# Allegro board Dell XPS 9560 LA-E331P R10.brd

Outline 352.7 x 122.8 mm; copper layers: TOP, GND1, IN1, IN2, GND2, IN3, IN4, VCC, IN5, IN6, GND3, BOTTOM. Coordinates in mm from the lower left corner of the outline.

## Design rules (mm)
net group CLK_PCIE_CR: nets CLK_PCIE_CR CLK_PCIE_CR#
net group CLK_PCIE_SSD: nets CLK_PCIE_SSD CLK_PCIE_SSD#
net group CLK_PCIE_WLAN: nets CLK_PCIE_WLAN CLK_PCIE_WLAN#
net group CRITICAL: nets CLINK_CLK SUSCLK
net group CSS_1: nets CSSN_1 CSSP_1
net group DDI1_CPU_AUX: nets DDI1_CPU_AUXN DDI1_CPU_AUXP
net group DDI1DDI1_CPU_AUX_C: nets DDI1_CPU_AUXN_C DDI1_CPU_AUXP_C
net group DDI1DDI1_HTX_TBRX_0: nets DDI1_HTX_TBRX_N0 DDI1_HTX_TBRX_P0
net group DDI1DDI1_HTX_TBRX_0_C: nets DDI1_HTX_TBRX_N0_C DDI1_HTX_TBRX_P0_C
net group DDI1DDI1_HTX_TBRX_1: nets DDI1_HTX_TBRX_N1 DDI1_HTX_TBRX_P1
net group DDI1DDI1_HTX_TBRX_1_C: nets DDI1_HTX_TBRX_N1_C DDI1_HTX_TBRX_P1_C
net group DDI1DDI1_HTX_TBRX_2: nets DDI1_HTX_TBRX_N2 DDI1_HTX_TBRX_P2
net group DDI1DDI1_HTX_TBRX_2_C: nets DDI1_HTX_TBRX_N2_C DDI1_HTX_TBRX_P2_C
net group DDI1DDI1_HTX_TBRX_3: nets DDI1_HTX_TBRX_N3 DDI1_HTX_TBRX_P3
net group DDI1DDI1_HTX_TBRX_3_C: nets DDI1_HTX_TBRX_N3_C DDI1_HTX_TBRX_P3_C
net group DDI1DDI2_CPU_AUX: nets DDI2_CPU_AUXN DDI2_CPU_AUXP
net group DDI1DDI2_CPU_AUX_C: nets DDI2_CPU_AUXN_C DDI2_CPU_AUXP_C
net group DDI1DDI2_HTX_TBRX_0: nets DDI2_HTX_TBRX_N0 DDI2_HTX_TBRX_P0
net group DDI1DDI2_HTX_TBRX_0_C: nets DDI2_HTX_TBRX_N0_C DDI2_HTX_TBRX_P0_C
net group DDI1DDI2_HTX_TBRX_1: nets DDI2_HTX_TBRX_N1 DDI2_HTX_TBRX_P1
net group DDI1DDI2_HTX_TBRX_1_C: nets DDI2_HTX_TBRX_N1_C DDI2_HTX_TBRX_P1_C
net group DDI1DDI2_HTX_TBRX_2: nets DDI2_HTX_TBRX_N2 DDI2_HTX_TBRX_P2
net group DDI1DDI2_HTX_TBRX_2_C: nets DDI2_HTX_TBRX_N2_C DDI2_HTX_TBRX_P2_C
net group DDI1DDI2_HTX_TBRX_3: nets DDI2_HTX_TBRX_N3 DDI2_HTX_TBRX_P3
net group DDI1DDI2_HTX_TBRX_3_C: nets DDI2_HTX_TBRX_N3_C DDI2_HTX_TBRX_P3_C
net group DIFFPAIR0: nets DDC_CLK_HDMI DDC_DAT_HDMI
net group DIFFPAIR35: nets USB3TN1_D- USB3TP1_D+
net group DIFFPAIR36: nets USB3RN1_D- USB3RP1_D+
net group DIFFPAIR47: nets SD_LN1_M SD_LN1_P
net group DIFFPAIR48: nets SD_LN0_M SD_LN0_P
net group DIFFPAIR49: nets SD_RCLK_M SD_RCLK_P
net group DIFFPAIR51: nets USB3RN1_RE USB3RP1_RE
net group DIFFPAIR57: nets DOCK_TNY_SMB_CLK DOCK_TNY_SMB_DAT
net group DIFFPAIR59: nets TBTA_I2C_C_N TBTA_I2C_C_P
net group DIFFPAIR60: nets TBTA_USB2_D_N_C TBTA_USB2_D_P_C
net group DIFFPAIR61: nets TBT_USB3_TX0_N TBT_USB3_TX0_P
net group DIFFPAIR62: nets TBT_USB3_TX1_N TBT_USB3_TX1_P
net group DIFFPAIR63: nets TBT_DDC_CLK TBT_DDC_DATA
net group DIFFPAIR64: nets XTAL_OUT XTALIN
net group EDP_AUXP_C: nets EDP_AUXN_C EDP_AUXP_C
net group EDP_TX2_R: nets EDP_TXN2_R EDP_TXP2_R
net group EDP_TX3_R: nets EDP_TXN3_R EDP_TXP3_R
net group FBA_CLK0: nets FBA_CLK0 FBA_CLK0#
net group FBA_CLK1: nets FBA_CLK1 FBA_CLK1#
net group FBA_WCK0: nets FBA_WCK0 FBA_WCK0_N
net group FBA_WCK1: nets FBA_WCK1 FBA_WCK1_N
net group FBA_WCK2: nets FBA_WCK2 FBA_WCK2_N
net group FBA_WCK3: nets FBA_WCK3 FBA_WCK3_N
net group FBC_CLK0: nets FBC_CLK0 FBC_CLK0#
net group FBC_CLK1: nets FBC_CLK1 FBC_CLK1#
net group FBC_WCK0: nets FBC_WCK0 FBC_WCK0_N
net group FBC_WCK1: nets FBC_WCK1 FBC_WCK1_N
net group FBC_WCK2: nets FBC_WCK2 FBC_WCK2_N
net group FBC_WCK3: nets FBC_WCK3 FBC_WCK3_N
net group PCIE_PRX_CARDTX_2: nets PCIE_PRX_CARDTX_N2 PCIE_PRX_CARDTX_P2
net group PCIE_PRX_CARDTX_2_C: nets PCIE_PRX_CARDTX_N2_C PCIE_PRX_CARDTX_P2_C
net group PCIE_PRX_SSDTX_10: nets PCIE_PRX_SSDTX_N10 PCIE_PRX_SSDTX_P10
net group PCIE_PRX_SSDTX_11: nets PCIE_PRX_SSDTX_N11 PCIE_PRX_SSDTX_P11
net group PCIE_PRX_SSDTX_12: nets PCIE_PRX_SSDTX_N12 PCIE_PRX_SSDTX_P12
net group PCIE_PRX_TBTX_15: nets PCIE_PRX_TBTX_N15 PCIE_PRX_TBTX_P15
net group PCIE_PRX_TBTX_16: nets PCIE_PRX_TBTX_N16 PCIE_PRX_TBTX_P16
net group PCIE_PRX_WLANTX_1: nets PCIE_PRX_WLANTX_N1 PCIE_PRX_WLANTX_P1
net group PCIE_PTX_CARDRX_2: nets PCIE_PTX_CARDRX_N2 PCIE_PTX_CARDRX_P2
net group PCIE_PTX_CARDRX_2_C: nets PCIE_PTX_CARDRX_N2_C PCIE_PTX_CARDRX_P2_C
net group PCIE_PTX_SSDRX_10: nets PCIE_PTX_SSDRX_N10 PCIE_PTX_SSDRX_P10
net group PCIE_PTX_SSDRX_10_C: nets PCIE_PTX_SSDRX_N10_C PCIE_PTX_SSDRX_P10_C
net group PCIE_PTX_SSDRX_11: nets PCIE_PTX_SSDRX_N11 PCIE_PTX_SSDRX_P11
net group PCIE_PTX_SSDRX_11_C: nets PCIE_PTX_SSDRX_N11_C PCIE_PTX_SSDRX_P11_C
net group PCIE_PTX_SSDRX_12: nets PCIE_PTX_SSDRX_N12 PCIE_PTX_SSDRX_P12
net group PCIE_PTX_SSDRX_12_C: nets PCIE_PTX_SSDRX_N12_C PCIE_PTX_SSDRX_P12_C
net group PCIE_PTX_TBRX_15: nets PCIE_PTX_TBRX_N15 PCIE_PTX_TBRX_P15
net group PCIE_PTX_TBRX_16: nets PCIE_PTX_TBRX_N16 PCIE_PTX_TBRX_P16
net group PCIE_PTX_WLANRX_1: nets PCIE_PTX_WLANRX_N1 PCIE_PTX_WLANRX_P1
net group PCIE_PTX_WLANRX_RE_1: nets PCIE_PTX_WLANRX_RE_N1 PCIE_PTX_WLANRX_RE_P1
net group REF-AGND: nets TBTA_CC1 TBTA_CC2
net group SATA_PRX_DTX_1B: nets SATA_PRX_DTX_N1B SATA_PRX_DTX_P1B
net group SATA_PRX_DTX_1B_RC: nets SATA_PRX_DTX_N1B_RC SATA_PRX_DTX_P1B_RC
net group SATA_PRX_SSDTX_0A: nets SATA_PRX_SSDTX_N0A SATA_PRX_SSDTX_P0A
net group SATA_PTX_DRX_1B: nets SATA_PTX_DRX_N1B SATA_PTX_DRX_P1B
net group SATA_PTX_DRX_1B_RC: nets SATA_PTX_DRX_N1B_RC SATA_PTX_DRX_P1B_RC
net group SATA_PTX_SSDRX_0A: nets SATA_PTX_SSDRX_N0A SATA_PTX_SSDRX_P0A
net group SATA_PTX_SSDRX_0A_C: nets SATA_PTX_SSDRX_N0A_C SATA_PTX_SSDRX_P0A_C
net group SD_RCLK_R: nets SD_RCLK_M_R SD_RCLK_P_R
net group SENSE: nets VCC_SENSE VSS_SENSE
net group SIN_CLK: nets AUD_AZA_CPU_SCLK VGA_CLK_REQ#
net group SMBUS: nets I2CB_SCL I2CB_SDA
net group SPI-CLK: nets PCH_SPI_CLK PCH_SPI_CLK_R
net group THERMTRIP: nets H_THERMTRIP# H_THERMTRIP#_R
net group USBP2_D: nets USBP2_D+ USBP2_D-
net group USBP2_R_D: nets USBP2_R_D+ USBP2_R_D-
net group 12: nets H_PECI UART2_RXD UART2_TXD
net group 15: nets HDA_BITCLK N121029055 N121029061
net group ASY: nets H_CPUPWRGD H_PROCHOT# H_PROCHOT#_R PCH_RSMRST#
net group ASYNCHRONOUS: nets DGPU_HOLD_RST#
net group AUDIO: nets HPOUT_D_L_C HPOUT_D_R_C HPOUT_L HPOUT_L_R1 HPOUT_R HPOUT_R_R2 LINE1-VREFO LINE1_L LINE1_L_C LINE1_R LINE1_R_C MIC1-VREFO_L MIC1-VREFO_R RING2 RING2_L SLEEVE SLEEVE_L
net group CLK_15_20: nets PCI_CLK_LPC1
net group DDI1: nets DDI1_DDPB_CTRLCLK DDI1_DDPB_CTRLDAT DDI1_PCH_HPD
net group DDI2: nets DDI2_DDPC_CTRLCLK DDI2_DDPC_CTRLDAT DDI2_PCH_HPD
net group DDR_CLK: nets M_CLK_DDR0 M_CLK_DDR1 M_CLK_DDR2 M_CLK_DDR3 M_CLK_DDR#0 M_CLK_DDR#1 M_CLK_DDR#2 M_CLK_DDR#3
net group DDR_DQS: nets DDR_A_DQS0 DDR_A_DQS1 DDR_A_DQS2 DDR_A_DQS3 DDR_A_DQS4 DDR_A_DQS5 DDR_A_DQS6 DDR_A_DQS7 DDR_A_DQS#0 DDR_A_DQS#1 DDR_A_DQS#2 DDR_A_DQS#3 DDR_A_DQS#4 DDR_A_DQS#5 DDR_A_DQS#6 DDR_A_DQS#7 DDR_B_DQS0 DDR_B_DQS1 DDR_B_DQS2 DDR_B_DQS3 DDR_B_DQS4 DDR_B_DQS5 DDR_B_DQS6 DDR_B_DQS7 DDR_B_DQS#0 DDR_B_DQS#1 DDR_B_DQS#2 DDR_B_DQS#3 DDR_B_DQS#4 DDR_B_DQS#5 DDR_B_DQS#6 DDR_B_DQS#7
net group DDRA_ADD: nets DDR_A_ACT# DDR_A_ALERT# DDR_A_BG0 DDR_A_BG1 DDR_A_BS0 DDR_A_BS1 DDR_A_CAS# DDR_A_MA0 DDR_A_MA1 DDR_A_MA2 DDR_A_MA3 DDR_A_MA4 DDR_A_MA5 DDR_A_MA6 DDR_A_MA7 DDR_A_MA8 DDR_A_MA9 DDR_A_MA10 DDR_A_MA11 DDR_A_MA12 DDR_A_MA13 DDR_A_PAR DDR_A_RAS# DDR_A_WE#
net group DDRA_CTRL: nets DDR_CKE0_DIMMA DDR_CKE1_DIMMA DDR_CS0_DIMMA# DDR_CS1_DIMMA# M_ODT0 M_ODT1
net group DDRA_D0: nets DDR_A_D0 DDR_A_D1 DDR_A_D2 DDR_A_D3 DDR_A_D4 DDR_A_D5 DDR_A_D6 DDR_A_D7
net group DDRA_D1: nets DDR_A_D8 DDR_A_D9 DDR_A_D10 DDR_A_D11 DDR_A_D12 DDR_A_D13 DDR_A_D14 DDR_A_D15
net group DDRA_D2: nets DDR_A_D16 DDR_A_D17 DDR_A_D18 DDR_A_D19 DDR_A_D20 DDR_A_D21 DDR_A_D22 DDR_A_D23
net group DDRA_D3: nets DDR_A_D24 DDR_A_D25 DDR_A_D26 DDR_A_D27 DDR_A_D28 DDR_A_D29 DDR_A_D30 DDR_A_D31
net group DDRA_D4: nets DDR_A_D32 DDR_A_D33 DDR_A_D34 DDR_A_D35 DDR_A_D36 DDR_A_D37 DDR_A_D38 DDR_A_D39
net group DDRA_D5: nets DDR_A_D40 DDR_A_D41 DDR_A_D42 DDR_A_D43 DDR_A_D44 DDR_A_D45 DDR_A_D46 DDR_A_D47
net group DDRA_D6: nets DDR_A_D48 DDR_A_D49 DDR_A_D50 DDR_A_D51 DDR_A_D52 DDR_A_D53 DDR_A_D54 DDR_A_D55
net group DDRA_D7: nets DDR_A_D56 DDR_A_D57 DDR_A_D58 DDR_A_D59 DDR_A_D60 DDR_A_D61 DDR_A_D62 DDR_A_D63
net group DDRB_ADD: nets DDR_B_ACT# DDR_B_ALERT# DDR_B_BG0 DDR_B_BG1 DDR_B_BS0 DDR_B_BS1 DDR_B_CAS# DDR_B_MA0 DDR_B_MA1 DDR_B_MA2 DDR_B_MA3 DDR_B_MA4 DDR_B_MA5 DDR_B_MA6 DDR_B_MA7 DDR_B_MA8 DDR_B_MA9 DDR_B_MA10 DDR_B_MA11 DDR_B_MA12 DDR_B_MA13 DDR_B_PAR DDR_B_RAS# DDR_B_WE#
net group DDRB_CTRL: nets DDR_CKE2_DIMMB DDR_CKE3_DIMMB DDR_CS2_DIMMB# DDR_CS3_DIMMB# M_ODT2 M_ODT3
net group DDRB_D0: nets DDR_B_D0 DDR_B_D1 DDR_B_D2 DDR_B_D3 DDR_B_D4 DDR_B_D5 DDR_B_D6 DDR_B_D7
net group DDRB_D1: nets DDR_B_D8 DDR_B_D9 DDR_B_D10 DDR_B_D11 DDR_B_D12 DDR_B_D13 DDR_B_D14 DDR_B_D15
net group DDRB_D2: nets DDR_B_D16 DDR_B_D17 DDR_B_D18 DDR_B_D19 DDR_B_D20 DDR_B_D21 DDR_B_D22 DDR_B_D23
net group DDRB_D3: nets DDR_B_D24 DDR_B_D25 DDR_B_D26 DDR_B_D27 DDR_B_D28 DDR_B_D29 DDR_B_D30 DDR_B_D31
net group DDRB_D4: nets DDR_B_D32 DDR_B_D33 DDR_B_D34 DDR_B_D35 DDR_B_D36 DDR_B_D37 DDR_B_D38 DDR_B_D39
net group DDRB_D5: nets DDR_B_D40 DDR_B_D41 DDR_B_D42 DDR_B_D43 DDR_B_D44 DDR_B_D45 DDR_B_D46 DDR_B_D47
net group DDRB_D6: nets DDR_B_D48 DDR_B_D49 DDR_B_D50 DDR_B_D51 DDR_B_D52 DDR_B_D53 DDR_B_D54 DDR_B_D55
net group DDRB_D7: nets DDR_B_D56 DDR_B_D57 DDR_B_D58 DDR_B_D59 DDR_B_D60 DDR_B_D61 DDR_B_D62 DDR_B_D63
net group DIFFPAIR38: nets USB3RP1
net group DMI: nets DMI_CRX_PTX_N0 DMI_CRX_PTX_N1 DMI_CRX_PTX_N2 DMI_CRX_PTX_N3 DMI_CRX_PTX_P0 DMI_CRX_PTX_P1 DMI_CRX_PTX_P2 DMI_CRX_PTX_P3 DMI_CTX_PRX_N0 DMI_CTX_PRX_N1 DMI_CTX_PRX_N2 DMI_CTX_PRX_N3 DMI_CTX_PRX_P0 DMI_CTX_PRX_P1 DMI_CTX_PRX_P2 DMI_CTX_PRX_P3
net group EDP: nets EDP_AUXN EDP_AUXN_R EDP_AUXP EDP_AUXP_R EDP_COMP EDP_HPD_S EDP_TXN0 EDP_TXN0_C EDP_TXN0_R EDP_TXN1 EDP_TXN1_C EDP_TXN1_R EDP_TXN2 EDP_TXN2_C EDP_TXN3 EDP_TXN3_C EDP_TXP0 EDP_TXP0_C EDP_TXP0_R EDP_TXP1 EDP_TXP1_C EDP_TXP1_R EDP_TXP2 EDP_TXP2_C EDP_TXP3 EDP_TXP3_C
net group FBA_CMD: nets FBA_ABI#_H FBA_ABI#_L FBA_CAS#_H FBA_CAS#_L FBA_CKE_H FBA_CKE_L FBA_CS#_H FBA_CS#_L FBA_MA0_MA10_H FBA_MA0_MA10_L FBA_MA1_MA9_H FBA_MA1_MA9_L FBA_MA2_BA0_H FBA_MA2_BA0_L FBA_MA3_BA3_H FBA_MA3_BA3_L FBA_MA4_BA2_H FBA_MA4_BA2_L FBA_MA5_BA1_H FBA_MA5_BA1_L FBA_MA6_MA11_H FBA_MA6_MA11_L FBA_MA7_MA8_H FBA_MA7_MA8_L FBA_MA12_RFU_H FBA_MA12_RFU_L FBA_RAS#_H FBA_RAS#_L FBA_RST#_H FBA_RST#_L FBA_WE#_H FBA_WE#_L
net group FBA_D0: nets FBA_D0 FBA_D1 FBA_D2 FBA_D3 FBA_D4 FBA_D5 FBA_D6 FBA_D7
net group FBA_D1: nets FBA_D8 FBA_D9 FBA_D10 FBA_D11 FBA_D12 FBA_D13 FBA_D14 FBA_D15
net group FBA_D2: nets FBA_D16 FBA_D17 FBA_D18 FBA_D19 FBA_D20 FBA_D21 FBA_D22 FBA_D23
net group FBA_D3: nets FBA_D24 FBA_D25 FBA_D26 FBA_D27 FBA_D28 FBA_D29 FBA_D30 FBA_D31
net group FBA_D4: nets FBA_D32 FBA_D33 FBA_D34 FBA_D35 FBA_D36 FBA_D37 FBA_D38 FBA_D39
net group FBA_D5: nets FBA_D40 FBA_D41 FBA_D42 FBA_D43 FBA_D44 FBA_D45 FBA_D46 FBA_D47
net group FBA_D6: nets FBA_D48 FBA_D49 FBA_D50 FBA_D51 FBA_D52 FBA_D53 FBA_D54 FBA_D55
net group FBA_D7: nets FBA_D56 FBA_D57 FBA_D58 FBA_D59 FBA_D60 FBA_D61 FBA_D62 FBA_D63
net group FBA_DBI: nets FBA_DBI0# FBA_DBI1# FBA_DBI2# FBA_DBI3# FBA_DBI4# FBA_DBI5# FBA_DBI6# FBA_DBI7#
net group FBA_EDC: nets FBA_EDC0 FBA_EDC1 FBA_EDC2 FBA_EDC3 FBA_EDC4 FBA_EDC5 FBA_EDC6 FBA_EDC7
net group FBC_CMD: nets FBC_ABI#_H FBC_ABI#_L FBC_CAS#_H FBC_CAS#_L FBC_CKE_H FBC_CKE_L FBC_CS#_H FBC_CS#_L FBC_MA0_MA10_H FBC_MA0_MA10_L FBC_MA1_MA9_H FBC_MA1_MA9_L FBC_MA2_BA0_H FBC_MA2_BA0_L FBC_MA3_BA3_H FBC_MA3_BA3_L FBC_MA4_BA2_H FBC_MA4_BA2_L FBC_MA5_BA1_H FBC_MA5_BA1_L FBC_MA6_MA11_H FBC_MA6_MA11_L FBC_MA7_MA8_H FBC_MA7_MA8_L FBC_MA12_RFU_H FBC_MA12_RFU_L FBC_RAS#_H FBC_RAS#_L FBC_RST#_H FBC_RST#_L FBC_WE#_H FBC_WE#_L
net group FBC_D0: nets FBC_D0 FBC_D1 FBC_D2 FBC_D3 FBC_D4 FBC_D5 FBC_D6 FBC_D7
net group FBC_D1: nets FBC_D8 FBC_D9 FBC_D10 FBC_D11 FBC_D12 FBC_D13 FBC_D14 FBC_D15
net group FBC_D2: nets FBC_D16 FBC_D17 FBC_D18 FBC_D19 FBC_D20 FBC_D21 FBC_D22 FBC_D23
net group FBC_D3: nets FBC_D24 FBC_D25 FBC_D26 FBC_D27 FBC_D28 FBC_D29 FBC_D30 FBC_D31
net group FBC_D4: nets FBC_D32 FBC_D33 FBC_D34 FBC_D35 FBC_D36 FBC_D37 FBC_D38 FBC_D39
net group FBC_D5: nets FBC_D40 FBC_D41 FBC_D42 FBC_D43 FBC_D44 FBC_D45 FBC_D46 FBC_D47
net group FBC_D6: nets FBC_D48 FBC_D49 FBC_D50 FBC_D51 FBC_D52 FBC_D53 FBC_D54 FBC_D55
net group FBC_D7: nets FBC_D56 FBC_D57 FBC_D58 FBC_D59 FBC_D60 FBC_D61 FBC_D62 FBC_D63
net group FBC_DBI: nets FBC_DBI0# FBC_DBI1# FBC_DBI2# FBC_DBI3# FBC_DBI4# FBC_DBI5# FBC_DBI6# FBC_DBI7#
net group FBC_EDC: nets FBC_EDC0 FBC_EDC1 FBC_EDC2 FBC_EDC3 FBC_EDC4 FBC_EDC5 FBC_EDC6 FBC_EDC7
net group GPU SENSE: nets GNDS_SENSE_VGA N128727776 N128727796 VDDS_SENSE_VGA
net group HDA: nets HDA_RST# HDA_SDIN0 HDA_SDOUT HDA_SDOUT_AUDIO HDA_SYNC HDA_SYNC_AUDIO I2S_BCLK I2S_IN I2S_LRCK I2S_MCLK I2S_OUT
net group HDA-CLK: nets HDA_BITCLK_AUDIO
net group HDMI: nets TMDS_L_TX0N TMDS_L_TX0P TMDS_L_TX1N TMDS_L_TX1P TMDS_L_TX2N TMDS_L_TX2P TMDS_L_TXCN TMDS_L_TXCP TMDS_TX0N TMDS_TX0P TMDS_TX1N TMDS_TX1P TMDS_TX2N TMDS_TX2P TMDS_TXCN TMDS_TXCP
net group LPC: nets LPC_AD0 LPC_AD1 LPC_AD2 LPC_AD3 LPC_FRAME#
net group PCIE-UT1: nets PCIE_PRX_TBTX_N15_C PCIE_PRX_TBTX_N16_C PCIE_PRX_TBTX_P15_C PCIE_PRX_TBTX_P16_C PCIE_PTX_TBRX_N15_C PCIE_PTX_TBRX_N16_C PCIE_PTX_TBRX_P15_C PCIE_PTX_TBRX_P16_C
net group PECI: nets PCH_PCIE_WAKE# PCH_PECI PCIE_WAKE#
net group PEG: nets PEG_GTX_C_HRX_N0 PEG_GTX_C_HRX_N1 PEG_GTX_C_HRX_N2 PEG_GTX_C_HRX_N3 PEG_GTX_C_HRX_N4 PEG_GTX_C_HRX_N5 PEG_GTX_C_HRX_N6 PEG_GTX_C_HRX_N7 PEG_GTX_C_HRX_N8 PEG_GTX_C_HRX_N9 PEG_GTX_C_HRX_N10 PEG_GTX_C_HRX_N11 PEG_GTX_C_HRX_N12 PEG_GTX_C_HRX_N13 PEG_GTX_C_HRX_N14 PEG_GTX_C_HRX_N15 PEG_GTX_C_HRX_P0 PEG_GTX_C_HRX_P1 PEG_GTX_C_HRX_P2 PEG_GTX_C_HRX_P3 PEG_GTX_C_HRX_P4 PEG_GTX_C_HRX_P5 PEG_GTX_C_HRX_P6 PEG_GTX_C_HRX_P7 PEG_GTX_C_HRX_P8 PEG_GTX_C_HRX_P9 PEG_GTX_C_HRX_P10 PEG_GTX_C_HRX_P11 PEG_GTX_C_HRX_P12 PEG_GTX_C_HRX_P13 PEG_GTX_C_HRX_P14 PEG_GTX_C_HRX_P15 PEG_GTX_HRX_N0 PEG_GTX_HRX_N1 PEG_GTX_HRX_N2 PEG_GTX_HRX_N3 PEG_GTX_HRX_N4 PEG_GTX_HRX_N5 PEG_GTX_HRX_N6 PEG_GTX_HRX_N7 PEG_GTX_HRX_N8 PEG_GTX_HRX_N9 PEG_GTX_HRX_N10 PEG_GTX_HRX_N11 PEG_GTX_HRX_N12 PEG_GTX_HRX_N13 PEG_GTX_HRX_N14 PEG_GTX_HRX_N15 PEG_GTX_HRX_P0 PEG_GTX_HRX_P1 PEG_GTX_HRX_P2 PEG_GTX_HRX_P3 PEG_GTX_HRX_P4 PEG_GTX_HRX_P5 PEG_GTX_HRX_P6 PEG_GTX_HRX_P7 PEG_GTX_HRX_P8 PEG_GTX_HRX_P9 PEG_GTX_HRX_P10 PEG_GTX_HRX_P11 PEG_GTX_HRX_P12 PEG_GTX_HRX_P13 PEG_GTX_HRX_P14 PEG_GTX_HRX_P15 PEG_HTX_C_GRX_N0 PEG_HTX_C_GRX_N1 PEG_HTX_C_GRX_N2 PEG_HTX_C_GRX_N3 PEG_HTX_C_GRX_N4 PEG_HTX_C_GRX_N5 PEG_HTX_C_GRX_N6 PEG_HTX_C_GRX_N7 PEG_HTX_C_GRX_N8 PEG_HTX_C_GRX_N9 PEG_HTX_C_GRX_N10 PEG_HTX_C_GRX_N11 PEG_HTX_C_GRX_N12 PEG_HTX_C_GRX_N13 PEG_HTX_C_GRX_N14 PEG_HTX_C_GRX_N15 PEG_HTX_C_GRX_P0 PEG_HTX_C_GRX_P1 PEG_HTX_C_GRX_P2 PEG_HTX_C_GRX_P3 PEG_HTX_C_GRX_P4 PEG_HTX_C_GRX_P5 PEG_HTX_C_GRX_P6 PEG_HTX_C_GRX_P7 PEG_HTX_C_GRX_P8 PEG_HTX_C_GRX_P9 PEG_HTX_C_GRX_P10 PEG_HTX_C_GRX_P11 PEG_HTX_C_GRX_P12 PEG_HTX_C_GRX_P13 PEG_HTX_C_GRX_P14 PEG_HTX_C_GRX_P15 PEG_HTX_GRX_N0 PEG_HTX_GRX_N1 PEG_HTX_GRX_N2 PEG_HTX_GRX_N3 PEG_HTX_GRX_N4 PEG_HTX_GRX_N5 PEG_HTX_GRX_N6 PEG_HTX_GRX_N7 PEG_HTX_GRX_N8 PEG_HTX_GRX_N9 PEG_HTX_GRX_N10 PEG_HTX_GRX_N11 PEG_HTX_GRX_N12 PEG_HTX_GRX_N13 PEG_HTX_GRX_N14 PEG_HTX_GRX_N15 PEG_HTX_GRX_P0 PEG_HTX_GRX_P1 PEG_HTX_GRX_P2 PEG_HTX_GRX_P3 PEG_HTX_GRX_P4 PEG_HTX_GRX_P5 PEG_HTX_GRX_P6 PEG_HTX_GRX_P7 PEG_HTX_GRX_P8 PEG_HTX_GRX_P9 PEG_HTX_GRX_P10 PEG_HTX_GRX_P11 PEG_HTX_GRX_P12 PEG_HTX_GRX_P13 PEG_HTX_GRX_P14 PEG_HTX_GRX_P15
net group PLATFORM CLK: nets CLK_PCIE_TBT CLK_PCIE_TBT# CLK_PEG_VGA CLK_PEG_VGA# CPU_24MHZ_N CPU_24MHZ_P PCH_CPU_BCLK_N PCH_CPU_BCLK_P PCH_CPU_PCIBCLK_N PCH_CPU_PCIBCLK_P PCH_XDP_CLK_N PCH_XDP_CLK_P
net group PLATFORM CLOCK-SE: nets CLK_PCI_MEC N120139517 SRCCLKREQ1# SRCCLKREQ2# SRCCLKREQ8# SRCCLKREQ9# SRCCLKREQ10# SRCCLKREQ11# SRCCLKREQ12# SRCCLKREQ13# SRCCLKREQ14# SRCCLKREQ15# XTAL24_IN XTAL24_OUT
net group PWR: nets +3V_PCH +3V_PS8723 +3VALWP +3VLP +5VALW +5VALWP +5VS_HDD +EDPVDD +INV_PWR_SRC +RTCBATT +RTCVCC +V_DDR_REF +V_DDR_REFA_R +V_DDR_REFB_R +VCHGR +VDISPLAY_VCC +VGA_B+
net group RTC: nets PCH_RTCRST# PCH_RTCX1 PCH_RTCX2 PCH_SRTCRST#
net group SD: nets SD_CD# SD_CLK SD_CLK_R SD_CMD SD_CMD_R SD_D2 SD_D2_R SD_D3 SD_D3_R SD_REG2
net group SMB: nets BC_CLK_ECE1117 BC_DAT_ECE1117 CHARGER_SCL CHARGER_SDA CHARGER_SMBCLK CHARGER_SMBDAT I2C0_SCK_DSP I2C0_SDA_DSP PBAT_SMBCLK PBAT_SMBDAT PCH_SMBCLK PCH_SMBDATA SMBCLK SMBDATA SML1_SMBCLK SML1_SMBDAT UPD_GPU_SMBCLK UPD_GPU_SMBDAT UPD_SMBCLK UPD_SMBDAT USBC_MCP23017_SMBCLK USBC_MCP23017_SMBDAT
net group SPI: nets PCH_SPI_CS1# PCH_SPI_CS2# PCH_SPI_CS# PCH_SPI_HOLD# PCH_SPI_HOLD#_R PCH_SPI_SI PCH_SPI_SI_R PCH_SPI_SO PCH_SPI_SO_R PCH_SPI_WP# PCH_SPI_WP#_R
net group SVID: nets VR_SVID_ALERT# VR_SVID_ALERT#_C VR_SVID_CLK VR_SVID_CLK_C VR_SVID_DATA VR_SVID_DATA_C
net group TBT: nets TBT_LSRX TBT_LSTX TBT_ML0_N TBT_ML0_P TBT_ML1_N TBT_ML1_P TBT_ML2_N TBT_ML2_P TBT_ML3_N TBT_ML3_P TBT_USB2_D+ TBT_USB2_D- TBT_USB3_TX0_N_C TBT_USB3_TX0_P_C TBTA_AUX_N TBTA_AUX_N_C TBTA_AUX_P TBTA_AUX_P_C TBTA_I2C_D_N TBTA_I2C_D_P TBTA_SBU1 TBTA_SBU2 TBTA_USB2_D_N_R TBTA_USB2_D_P_R
net group TBT_RX/TX: nets TBT_USB3_RX0_N TBT_USB3_RX0_P TBT_USB3_RX1_N TBT_USB3_RX1_P TBT_USB3_TX1_N_C TBT_USB3_TX1_P_C
net group THERMAL DIODE: nets REM_DIODE1_N REM_DIODE1_P REM_DIODE2_N REM_DIODE2_P REM_DIODE3_N REM_DIODE3_P REM_DIODE4_N REM_DIODE4_P
net group USB2.0: nets USB20_FP_N1_CONN USB20_FP_P1_CONN USB20_N1 USB20_N2 USB20_N4 USB20_N4_R USB20_N7 USB20_N9 USB20_N9_R USB20_N12 USB20_N12_R USB20_P1 USB20_P2 USB20_P4 USB20_P4_R USB20_P7 USB20_P9_R USB20_P12 USB20_P12_R
net group USB3.0: nets USB3RN1 USB3RN1_C USB3RN2 USB3RN2_D- USB3RP1_C USB3RP2 USB3RP2_D+ USB3T_N1 USB3T_N2 USB3T_P1 USB3T_P2 USB3TN1 USB3TN1_C USB3TN1_RE USB3TN2 USB3TN2_D- USB3TP1 USB3TP1_C USB3TP1_RE USB3TP2 USB3TP2_D+ USBP1_D+ USBP1_D- USBP1_R_D+ USBP1_R_D-
net group USB20_N9: nets USB20_P9
nets with their own width: min track width 0.203; nets VCC1V8A_TBTA_LDO
nets with their own width: min track width 0.254; nets 1V8_3V3_MAIN_RUN_EN GPU_CORE_PG N132908405 N132908425 N132908471 N132908575 N132908582 N132957909 NVVDD_EN NVVDDS_EN VCC_3V3_PCIE VCC_3V3_USB2
nets with their own width: min track width 0.305; nets N121070696
nets with their own width: min track width 0.381; nets 1V8_3V3_MAIN_EN N130500830
nets with their own width: min track width 0.508; nets +0.6VS +0.6VSP +0.95VSP +1.2V_DDR +1.2V_MEN_P +1.2V_PWROK +1.2V_VCCPLL_OC +1.8V_3.3V_GFX_AON +1.8V_3.3V_GFX_RUN +1.35V_VSNS +1.35VSDGPU +1V_MPHY +1V_PCH +1V_PCH_AZPLL +1V_PCH_PRIM +1V_VCCDSW +1VALW +1VSP +3.3V_ALW_DEG +3V_PCH_AZIO +3V_PCH_DSW +3V_PCH_SPI +3V_ROM +3V_TBT +3V_TBT_PWR +3VA_TBT +3VA_TBT_LC +3VALW +3VALW_5085 +3VALW_23017 +3VS_CAM +3VS_CR +3VS_FFS +3VS_TP +3VS_TPM +3VS_TPM_VSB +3VS_TS +3VS_WLAN +5V_CHGUSB_1 +5V_CHGUSB_2 +5VS +AC_IN +DC_IN +DC_IN_SS +GPU_CORE +GPU_CORE_VDDS +ODR_PWR +PWR_SRC_AC +RTC_CELL_VBAT +SD_VDD2 +SDC_IN +V_DDR_REFA +V_DDR_REFB +VBUS_1 +VBUS_DC_SS +VCC0V9_PCIE +VCC0V9_USB +VCC_CORE +VCCGT +VCCIO +VCCSA +VCCST +VCCSTG +VLDOIN_1.2V +VR_CAP AGND B+ B++ DGPU_PEX_RST# GND MEM_VREF TBTA_VBUS_L VCC3V3_FLASH VCC5V0_SYS
nets with their own width: min track width 1.524; nets +3VS
nets with their own width: min track width 2.54; nets +3.3VDX_SSD

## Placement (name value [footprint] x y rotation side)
ADP100  ACES_50290-00701-001  [ACES_50290-00701-001_7P-T]  14.85 75.74 0 bottom
BAT100  ACES_50290-01201-P01  [ACES_50290-01201-P01_12P-T]  28.35 14.64 180 bottom
C2973  2.2U_0603_25V6K  [C_0603]  217.34 11.85 90 bottom
C2974  0.1U_0402_10V7K  [C_0402]  218.4 7.73 90 bottom
CA1  0.1U_0201_6.3V6K  [C_0201]  13.46 34.81 270 top
CA2  10U_0402_6.3V6M  [C_0402]  14.02 36.46 0 top
CA3  0.1U_0201_6.3V6K  [C_0201]  12.68 38.11 180 top
CA4  10U_0402_6.3V6M  [C_0402]  12.65 37.28 180 top
CA5  0.1U_0201_6.3V6K  [C_0201]  13.4 41.02 90 bottom
CA6  10U_0402_6.3V6M  [C_0402]  14.12 41.08 90 bottom
CA7  10U_0402_6.3V6M  [C_0402]  14.99 41.08 90 bottom
CA8  0.1U_0201_6.3V6K  [C_0201]  15.14 37.85 0 bottom
CA9  10U_0402_6.3V6M  [C_0402]  15.1 37.09 0 bottom
CA10  0.1U_0201_6.3V6K  [C_0201]  13.53 39.04 270 bottom
CA11  10U_0402_6.3V6M  [C_0402]  14.25 39.46 270 bottom
CA12  0.1U_0201_6.3V6K  [C_0201]  3.08 39.75 180 top
CA13  10U_0402_6.3V6M  [C_0402]  3.25 41.41 180 top
CA14  10U_0402_6.3V6M  [C_0402]  3.25 40.52 180 top
CA15  2.2U_0603_6.3V6K  [C_0603]  3.68 39.75 180 bottom
CA16  0.1U_0201_6.3V6K  [C_0201]  2.25 38.81 0 bottom
CA17  0.1U_0201_6.3V6K  [C_0201]  3.09 39.06 180 top
CA18  2.2U_0603_6.3V6K  [C_0603]  3.68 41.09 180 bottom
CA19  100P_0201_25V8J  [C_0201]  2.24 29.21 0 top
CA20  2.2U_0603_6.3V6K  [C_0603]  2.82 42.31 90 bottom
CA21  2.2U_0603_6.3V6K  [C_0603]  5.59 43.38 180 bottom
CA23  0.1U_0201_6.3V6K  [C_0201]  5.25 29.15 270 bottom
CA24  0.1U_0201_6.3V6K  [C_0201]  12.99 43.51 180 bottom
CA25  2.2U_0402_6.3V6M  [C_0402]  13.02 44.32 90 bottom
CA26  0.1U_0201_6.3V6K  [C_0201]  2.82 37.6 0 top
CA27  10U_0402_6.3V6M  [C_0402]  2.73 36.85 270 top
CA28  0.1U_0201_6.3V6K  [C_0201]  2.83 37.6 180 bottom
CA29  4.7U_0402_6.3V6M  [C_0402]  2.8 36.85 270 bottom
CA30  10U_0402_6.3V6M  [C_0402]  13.97 44.32 90 bottom
CA31  10U_0402_6.3V6M  [C_0402]  11.47 43.2 90 bottom
CA32  0.1U_0201_6.3V6K  [C_0201]  9.06 33.24 180 bottom
CA33  10P_0201_50V8J  [C_0201]  4.79 32.98 180 bottom
CA34  10P_0201_50V8J  [C_0201]  4.87 33.6 180 bottom
CA35  10P_0201_50V8J  [C_0201]  14.73 34.81 270 bottom
CA36  10P_0201_50V8J  [C_0201]  13.4 35 270 bottom
CA37  10P_0201_50V8J  [C_0201]  4.67 29.13 270 bottom
CA38  10P_0201_50V8J  [C_0201]  4.07 30.78 0 top
CA39  4.7U_0402_6.3V6M  [C_0402]  5.29 32.54 270 top
CA40  0.1U_0201_6.3V6K  [C_0201]  4.32 36.36 90 top
CA41  680P_0402_50V7K  [C_0402]  5 59.31 270 top
CA42  680P_0402_50V7K  [C_0402]  14.81 54.49 180 top
CA43  680P_0402_50V7K  [C_0402]  13.97 46.82 270 top
CA44  680P_0402_50V7K  [C_0402]  5.26 45.04 270 top
CA45  10U_0402_6.3V6M  [C_0402]  8.18 42.81 0 top
CA77  4.7U_0402_6.3V6M  [C_0402]  4.51 34.25 270 top
CA78  4.7U_0402_6.3V6M  [C_0402]  9.35 32.48 180 bottom
CA119  10U_0402_6.3V6M  [C_0402]  8.18 41.92 0 top
CA120  22P_0201_25V8  [C_0201]  4.2 32.34 0 bottom
CA121  1U_0201_6.3V6M  [C_0201]  5.98 10.64 0 bottom
CA122  1U_0201_6.3V6M  [C_0201]  6.58 16.04 0 bottom
CA124  470P_0201_25V7K  [C_0201]  9.11 8.8 90 top
CA125  1000P_0201_16V7K  [C_0201]  9.87 8.8 90 top
CA126  1U_0201_6.3V6M  [C_0201]  8.15 3.84 0 top
CA127  1U_0201_6.3V6M  [C_0201]  11.8 5.03 0 top
CA128  10U_0402_6.3V6M  [C_0402]  6.58 10.41 270 top
CA129  10U_0402_6.3V6M  [C_0402]  11.99 10.79 270 top
CA130  0.1U_0201_6.3V6K  [C_0201]  4.32 35.61 270 top
CA137  0.68U_0603_16V6K  [C_0603]  5.08 9.66 180 bottom
CD1  1U_0402_6.3V6K  [C_0402]  147.77 27.56 90 top
CD2  1U_0402_6.3V6K  [C_0402]  136.12 28.53 270 top
CD3  1U_0402_6.3V6K  [C_0402]  174.29 28.98 0 top
CD4  1U_0402_6.3V6K  [C_0402]  174.29 28.1 0 top
CD5  10U_0603_6.3V6M  [C_0603]  149.54 27.25 90 top
CD6  10U_0603_6.3V6M  [C_0603]  141.55 18.46 0 top
CD7  10U_0603_6.3V6M  [C_0603]  157.44 63.19 0 top
CD8  10U_0603_6.3V6M  [C_0603]  138.62 28.65 270 top
CD9  10U_0603_6.3V6M  [C_0603]  173.98 27.02 0 top
CD10  10U_0603_6.3V6M  [C_0603]  173.98 25.81 0 top
CD11  220U_D7_2VM_R6M  [C_EEFSS0D221R]  133.73 50.57 0 top
CD12  1U_0402_6.3V6K  [C_0402]  173.8 17.8 90 top
CD13  10U_0603_6.3V6M  [C_0603]  174.88 17.6 90 top
CD14  10U_0603_6.3V6M  [C_0603]  176.15 17.47 90 top
CD15  10U_0603_6.3V6M  [C_0603]  177.42 17.47 90 top
CD16  .1U_0402_16V7K  [C_0402]  171.82 26.88 180 top
CD17  2.2U_0402_6.3V6M  [C_0402]  171.93 25.8 180 top
CD18  .1U_0402_16V7K  [C_0402]  150.19 17.65 90 top
CD19  1U_0402_6.3V6K  [C_0402]  211.48 17.71 90 top
CD20  1U_0402_6.3V6K  [C_0402]  212.93 17.71 90 top
CD21  1U_0402_6.3V6K  [C_0402]  212.42 28.53 270 top
CD22  1U_0402_6.3V6K  [C_0402]  215.87 17.71 90 top
CD23  10U_0603_6.3V6M  [C_0603]  217.08 28.65 270 top
CD24  10U_0603_6.3V6M  [C_0603]  217.85 18.42 0 top
CD25  10U_0603_6.3V6M  [C_0603]  214.92 28.65 270 top
CD26  10U_0603_6.3V6M  [C_0603]  211.39 28.65 270 top
CD27  10U_0603_6.3V6M  [C_0603]  250.18 27.38 0 top
CD28  10U_0603_6.3V6M  [C_0603]  250.11 26.12 0 top
CD29  .1U_0402_16V7K  [C_0402]  226.5 17.65 90 top
CD30  1U_0402_6.3V6K  [C_0402]  251.46 29.51 0 top
CD31  1U_0402_6.3V6K  [C_0402]  250.84 28.48 0 top
CD32  1U_0402_6.3V6K  [C_0402]  250.33 17.46 90 top
CD33  220U_D7_2VM_R6M  [C_EEFSS0D221R]  147.2 50.57 0 top
CD34  .1U_0402_16V7K  [C_0402]  248.91 26.87 180 top
CD35  2.2U_0402_6.3V6M  [C_0402]  249.02 25.79 180 top
CD36  4.7U_0603_6.3V6K  [C_0603]  268.1 22.04 270 top
CD37  0.22U_0402_10V6K  [C_0402]  257.1 20.2 0 bottom
CD38  .1U_0402_16V7K  [C_0402]  268.43 19.57 180 top
CD39  0.01U_0402_16V7K  [C_0402]  268.43 18.55 180 top
CD40  47P_0402_50V8J  [C_0402]  268.43 4.45 180 top
CD41  15P_0402_50V8J  [C_0402]  268.43 5.47 180 top
CD42  0.22U_0402_10V6K  [C_0402]  257.1 19.31 0 bottom
CD43  0.22U_0402_10V6K  [C_0402]  257.1 17.15 0 bottom
CD44  0.22U_0402_10V6K  [C_0402]  257.1 16.26 0 bottom
CD45  0.22U_0402_10V6K  [C_0402]  257.1 14.23 0 bottom
CD46  0.22U_0402_10V6K  [C_0402]  257.1 13.34 0 bottom
CD47  0.1U_0402_10V7K  [C_0402]  254.89 6.24 270 bottom
CD51  0.22U_0402_10V6K  [C_0402]  257.1 10.3 0 bottom
CD53  0.22U_0402_10V6K  [C_0402]  257.1 11.18 0 bottom
CD69  .1U_0402_16V7K  [C_0402]  133.22 18.73 270 top
CD70  10U_0603_6.3V6M  [C_0603]  145.94 17.28 90 top
CD71  10U_0603_6.3V6M  [C_0603]  148.65 17.28 90 top
CD72  10U_0603_6.3V6M  [C_0603]  140.78 28.65 270 top
CD73  10U_0603_6.3V6M  [C_0603]  135.09 28.65 270 top
CD74  1U_0402_6.3V6K  [C_0402]  139.57 17.81 90 top
CD75  1U_0402_6.3V6K  [C_0402]  138.15 17.81 90 top
CD76  1U_0402_6.3V6K  [C_0402]  136.63 17.81 90 top
CD77  1U_0402_6.3V6K  [C_0402]  135.18 17.81 90 top
CD78  1U_0402_6.3V6K  [C_0402]  143.56 28.53 270 top
CD79  1U_0402_6.3V6K  [C_0402]  142.16 28.53 270 top
CD80  1U_0402_6.3V6K  [C_0402]  224.07 27.56 90 top
CD81  1U_0402_6.3V6K  [C_0402]  219.86 28.53 270 top
CD82  1U_0402_6.3V6K  [C_0402]  218.46 28.53 270 top
CD83  1U_0402_6.3V6K  [C_0402]  214.45 17.71 90 top
CD84  10U_0603_6.3V6M  [C_0603]  229.6 19.58 180 top
CD85  10U_0603_6.3V6M  [C_0603]  225.84 27.25 90 top
CD86  10U_0603_6.3V6M  [C_0603]  224.95 17.28 90 top
CD87  10U_0603_6.3V6M  [C_0603]  222.24 17.28 90 top
CD88  10U_0603_6.3V6M  [C_0603]  253.95 17.47 90 top
CD89  10U_0603_6.3V6M  [C_0603]  252.68 17.47 90 top
CD90  10U_0603_6.3V6M  [C_0603]  251.41 17.47 90 top
CE2  0.1U_0402_10V6K  [C_0402]  190.39 7.97 270 top
CE8  27P_0402_50V8J  [C_0402]  150.22 9.47 90 top
CE11  0.1U_0402_25V6  [C_0402]  158.24 4.91 0 top
CE12  0.1U_0402_25V6  [C_0402]  149.8 5.66 180 top
CE13  0.1U_0402_25V6  [C_0402]  153.62 11.69 180 top
CE14  10U_0603_6.3V6M  [C_0603]  150.05 4.58 180 top
CE15  .1U_0402_16V7K  [C_0402]  349.51 116.73 270 top
CE16  10P_0402_25V8J  [C_0402]  348.04 116.73 270 top
CE17  0.1U_0402_25V6  [C_0402]  291.21 12.79 270 top
CE18  0.1U_0402_25V6  [C_0402]  306.38 14.11 0 top
CE19  1U_0402_6.3V6K  [C_0402]  306.38 13.22 0 top
CE20  0.1U_0402_25V6  [C_0402]  291.21 14.94 270 top
CE21  1U_0402_6.3V6K  [C_0402]  290.32 14.94 270 top
CE22  10U_0603_6.3V6M  [C_0603]  308.99 21.47 0 top
CE23  0.1U_0402_25V6  [C_0402]  304.55 23.3 90 top
CE24  0.1U_0402_25V6  [C_0402]  301.5 7.45 270 top
CE25  0.1U_0402_25V6  [C_0402]  306.38 16.14 0 top
CE26  0.1U_0402_25V6  [C_0402]  293.93 7.45 270 top
CE27  0.1U_0402_25V6  [C_0402]  299.09 23.3 90 top
CE28  0.1U_0402_25V6  [C_0402]  291.16 17.66 180 top
CE29  1U_0402_6.3V6K  [C_0402]  292.99 4.06 90 top
CE30  1U_0402_6.3V6K  [C_0402]  293.05 7.45 270 top
CE31  0.047U_0402_25V7K  [C_0402]  306.33 11.9 270 top
CE32  2200P_0402_25V7K  [C_0402]  303.79 6.54 90 top
CE33  2200P_0402_25V7K  [C_0402]  304.67 6.47 90 top
CE34  0.1U_0402_25V6  [C_0402]  291.16 22.11 180 top
CE35  2200P_0402_25V7K  [C_0402]  305.56 7.39 270 top
CE36  2200P_0402_25V7K  [C_0402]  307.02 6.54 90 top
CE37  1U_0402_6.3V6K  [C_0402]  285.75 14.94 270 top
CE38  1U_0402_6.3V6K  [C_0402]  288.93 14.03 90 top
CE39  47P_0402_50V8J  [C_0402]  294.01 23.3 90 top
CE40  4.7U_0603_6.3V6K  [C_0603]  302.64 7.31 270 top
CE41  0.1U_0402_25V6  [C_0402]  306.3 10.08 0 top
CE42  22P_0402_50V8J  [C_0402]  288.93 12.91 270 top
CE43  22P_0402_50V8J  [C_0402]  288.93 10.22 90 top
CE44  1U_0402_6.3V6K  [C_0402]  297.1 23.38 0 top
CE45  100P_0402_50V8J  [C_0402]  115.3 111.88 270 bottom
CE46  100P_0402_50V8J  [C_0402]  173.17 116.54 0 bottom
CE47  100P_0402_50V8J  [C_0402]  180.63 74.85 0 top
CE48  4.7P_0402_50V8C  [C_0402]  308.15 17.66 0 top
CE49  100P_0402_50V8J  [C_0402]  180.21 49.08 90 bottom
CE50  100P_0402_50V8J  [C_0402]  281.89 25.41 180 bottom
CE51  4700P_0402_25V7K  [C_0402]  298.71 7.45 270 top
CE52  0.1U_0402_25V6  [C_0402]  306.33 19.9 270 top
CE53  10U_0603_6.3V6M  [C_0603]  274.83 8.45 270 top
CE54  0.1U_0402_25V6  [C_0402]  278.56 8.39 0 top
CE55  0.1U_0402_25V6  [C_0402]  278.56 9.28 0 top
CE65  2200P_0402_25V7K  [C_0402]  192.79 8.86 0 top
CE66  0.01U_0402_16V7K  [C_0402]  100.33 34.81 90 top
CE67  0.01U_0402_16V7K  [C_0402]  322.84 38.31 270 top
CE68  100P_0402_50V8J  [C_0402]  27.04 51.44 0 top
CE69  100P_0402_50V8J  [C_0402]  158.33 72.08 0 top
CE70  1U_0402_6.3V6K  [C_0402]  291.48 6.3 180 top
CE71  1U_0402_6.3V6K  [C_0402]  289.05 4.12 90 top
CE72  100P_0402_50V8J  [C_0402]  242.27 106.31 180 bottom
CE73  4.7P_0402_50V8C  [C_0402]  154.38 9.03 180 bottom
CE74  4.7P_0402_50V8C  [C_0402]  154.37 10.82 270 bottom
CE75  0.1U_0402_25V6  [C_0402]  158.17 9.15 0 top
CE76  10U_0603_6.3V6M  [C_0603]  158.18 10.3 0 top
CE77  22P_0402_50V8J  [C_0402]  185.77 5.68 180 top
CE78  22P_0402_50V8J  [C_0402]  186.85 7.59 180 top
CE79  22P_0402_50V8J  [C_0402]  187.85 12.91 90 bottom
CE80  22P_0402_50V8J  [C_0402]  186.9 12.91 90 bottom
CE81  4.7P_0402_50V8C  [C_0402]  165.15 8.64 0 bottom
CE82  4.7P_0402_50V8C  [C_0402]  165.15 9.53 0 bottom
CE83  10U_0603_6.3V6M  [C_0603]  153.54 6.36 180 bottom
CF1  10U_0603_6.3V6M  [C_0603]  240.44 45.87 270 top
CF2  0.1U_0402_25V6  [C_0402]  238.39 51.11 90 top
CH3  0.1U_0402_25V6  [C_0402]  121.79 95.47 270 bottom
CH5  0.22U_0201_6.3V6M  [C_0201]  189.45 82.05 0 bottom
CH6  0.22U_0201_6.3V6M  [C_0201]  189.45 82.69 0 bottom
CH7  0.22U_0201_6.3V6M  [C_0201]  187.99 80.97 0 bottom
CH8  0.22U_0201_6.3V6M  [C_0201]  187.99 81.61 0 bottom
CH9  0.22U_0201_6.3V6M  [C_0201]  189.45 79.7 0 bottom
CH10  0.22U_0201_6.3V6M  [C_0201]  189.45 80.34 0 bottom
CH11  0.22U_0201_6.3V6M  [C_0201]  187.99 79.22 0 bottom
CH12  0.22U_0201_6.3V6M  [C_0201]  187.99 78.59 0 bottom
CH13  0.22U_0201_6.3V6M  [C_0201]  189.45 77.35 0 bottom
CH14  0.22U_0201_6.3V6M  [C_0201]  189.45 77.99 0 bottom
CH15  0.22U_0201_6.3V6M  [C_0201]  188.18 76.91 0 bottom
CH16  0.22U_0201_6.3V6M  [C_0201]  188.18 76.27 0 bottom
CH17  0.22U_0201_6.3V6M  [C_0201]  190.02 75.45 0 bottom
CH18  0.22U_0201_6.3V6M  [C_0201]  190.02 76.08 0 bottom
CH19  0.22U_0201_6.3V6M  [C_0201]  188.56 74.43 0 bottom
CH20  0.22U_0201_6.3V6M  [C_0201]  188.56 75.07 0 bottom
CH21  0.22U_0201_6.3V6M  [C_0201]  190.02 74.05 0 bottom
CH22  0.22U_0201_6.3V6M  [C_0201]  190.02 73.41 0 bottom
CH23  0.22U_0201_6.3V6M  [C_0201]  188.62 72.46 0 bottom
CH24  0.22U_0201_6.3V6M  [C_0201]  188.62 73.1 0 bottom
CH25  0.22U_0201_6.3V6M  [C_0201]  190.02 72.02 0 bottom
CH26  0.22U_0201_6.3V6M  [C_0201]  190.02 71.38 0 bottom
CH27  0.22U_0201_6.3V6M  [C_0201]  188.62 70.3 0 bottom
CH28  0.22U_0201_6.3V6M  [C_0201]  188.62 70.94 0 bottom
CH29  0.22U_0201_6.3V6M  [C_0201]  190.02 69.92 0 bottom
CH30  0.22U_0201_6.3V6M  [C_0201]  190.02 69.29 0 bottom
CH31  0.22U_0201_6.3V6M  [C_0201]  188.68 67.76 0 bottom
CH32  0.22U_0201_6.3V6M  [C_0201]  188.68 68.4 0 bottom
CH33  0.22U_0201_6.3V6M  [C_0201]  190.08 67.26 0 bottom
CH34  0.22U_0201_6.3V6M  [C_0201]  190.08 66.62 0 bottom
CH35  0.22U_0201_6.3V6M  [C_0201]  189.32 65.08 0 bottom
CH36  0.22U_0201_6.3V6M  [C_0201]  189.32 65.71 0 bottom
CH44  1U_0402_6.3V6K  [C_0402]  346.37 83.57 0 top
CH45  8.2P_0402_50V8D  [C_0402]  98.86 2.74 0 top
CH46  8.2P_0402_50V8D  [C_0402]  98.86 1.81 0 top
CH47  15P_0201_50V8J  [C_0201]  103.13 26.64 90 top
CH48  15P_0201_50V8J  [C_0201]  103.2 26.03 270 top
CH50  10P_0402_25V8J  [C_0402]  103.46 3.95 180 bottom
CH51  10P_0402_25V8J  [C_0402]  96.37 6.07 0 top
CH52  1U_0402_6.3V6K  [C_0402]  94.11 5.22 180 top
CH53  1U_0402_6.3V6K  [C_0402]  105.78 4.05 270 top
CH70  0.1U_0402_10V7K  [C_0402]  86.69 4.83 180 top
CH80  1U_0402_6.3V6K  [C_0402]  89.12 7.9 90 top
CH82  1U_0402_6.3V6K  [C_0402]  92.76 16.77 0 top
CH100  0.022U_0402_25V7K  [C_0402]  231.31 19.39 270 top
CH101  0.022U_0402_25V7K  [C_0402]  122 19.24 270 top
CH102  10U_0603_6.3V6M  [C_0603]  173.15 71.32 270 top
CH103  10U_0603_6.3V6M  [C_0603]  173.07 73.73 270 top
CH104  10U_0603_6.3V6M  [C_0603]  173.06 76.09 90 top
CH105  1U_0402_6.3V6K  [C_0402]  175.29 83.32 0 top
CH106  1U_0402_6.3V6K  [C_0402]  174.91 82.44 0 top
CH107  1U_0402_6.3V6K  [C_0402]  173.1 79.28 0 top
CH108  1U_0402_6.3V6K  [C_0402]  173.29 80.66 180 top
CH109  1U_0402_6.3V6K  [C_0402]  174.91 81.17 0 top
CH110  1U_0402_6.3V6K  [C_0402]  173 78.41 0 top
CH111  10U_0603_6.3V6M  [C_0603]  170.36 83.13 270 top
CH112  10U_0603_6.3V6M  [C_0603]  174.8 86.12 90 top
CH113  10U_0603_6.3V6M  [C_0603]  173.59 86.12 90 top
CH114  10U_0603_6.3V6M  [C_0603]  178.4 86.06 90 top
CH115  10U_0603_6.3V6M  [C_0603]  170.38 85.23 90 top
CH116  10U_0603_6.3V6M  [C_0603]  172.64 84.97 0 top
CH117  10U_0603_6.3V6M  [C_0603]  177.22 85.04 270 top
CH118  22U_0603_6.3V6M  [C_0603]  151.11 66.62 90 top
CH119  10U_0603_6.3V6M  [C_0603]  155.89 66.37 90 top
CH120  22U_0603_6.3V6M  [C_0603]  170.36 62.76 90 top
CH121  22U_0603_6.3V6M  [C_0603]  149.12 64.51 0 top
CH122  10U_0603_6.3V6M  [C_0603]  157.59 65.99 90 top
CH123  10U_0603_6.3V6M  [C_0603]  163.84 62.52 180 top
CH124  22U_0603_6.3V6M  [C_0603]  149.46 66.62 90 top
CH125  10U_0603_6.3V6M  [C_0603]  161.22 65.32 90 top
CH126  10U_0603_6.3V6M  [C_0603]  167.8 62.73 90 top
CH127  10U_0603_6.3V6M  [C_0603]  171.63 67.5 180 top
CH128  10U_0603_6.3V6M  [C_0603]  173.05 62.4 0 top
CH129  22U_0603_6.3V6M  [C_0603]  168.25 50.23 0 top
CH130  22U_0603_6.3V6M  [C_0603]  168.25 48.51 0 top
CH131  22U_0603_6.3V6M  [C_0603]  168.25 46.73 0 top
CH132  22U_0603_6.3V6M  [C_0603]  168.25 44.89 0 top
CH133  1U_0402_6.3V6K  [C_0402]  172.55 86.04 90 top
CH134  1U_0402_6.3V6K  [C_0402]  170.99 87.55 180 top
CH135  1U_0402_6.3V6K  [C_0402]  171 84.09 180 top
CH136  47U_0603_6.3V6M  [C_0603]  171.58 89.67 90 bottom
CH138  330U_B2_2.5VM_R9M  [C_B2]  170.1 93.29 0 bottom
CH173  0.1U_0402_10V7K  [C_0402]  88.23 7.9 90 top
CH174  0.1U_0402_25V6  [C_0402]  130.47 94.65 270 top
CH175  0.1U_0402_25V6  [C_0402]  122.68 95.46 270 bottom
CH176  1U_0402_6.3V6K  [C_0402]  85.59 6.57 90 top
CH177  22U_0603_6.3V6M  [C_0603]  102.3 17.12 270 bottom
CH178  22U_0603_6.3V6M  [C_0603]  102.3 20.04 270 bottom
CH179  1U_0402_6.3V6K  [C_0402]  101.84 21.15 0 bottom
CH180  1U_0402_6.3V6K  [C_0402]  76.98 27.19 180 top
CH181  22U_0603_6.3V6M  [C_0603]  77.34 29.07 90 top
CH182  22U_0603_6.3V6M  [C_0603]  79.12 29.07 90 top
CH183  1U_0402_6.3V6K  [C_0402]  86.5 18.36 180 top
CH184  22U_0603_6.3V6M  [C_0603]  83.06 32.18 90 top
CH186  0.1U_0402_10V7K  [C_0402]  91.44 6.41 90 top
CH187  1U_0402_6.3V6K  [C_0402]  99.23 3.7 0 top
CH188  1U_0402_6.3V6K  [C_0402]  93.71 14.36 0 top
CH189  0.1U_0402_10V7K  [C_0402]  97.65 9.98 0 top
CH190  0.1U_0402_10V7K  [C_0402]  79.52 14.49 180 top
CH191  0.1U_0402_10V7K  [C_0402]  79.2 10.93 180 top
CH192  0.1U_0402_10V7K  [C_0402]  77.09 4.34 270 top
CH196  15P_0402_50V8J  [C_0402]  89.16 6.89 180 top
CH197  0.1U_0402_10V7K  [C_0402]  121.37 53.18 180 top
CH198  15P_0402_50V8J  [C_0402]  108.28 4.07 0 bottom
CH199  15P_0402_50V8J  [C_0402]  109.21 4.96 0 bottom
CH200  0.1U_0402_10V7K  [C_0402]  92.67 6.64 0 top
CH201  22U_0603_6.3V6M  [C_0603]  105.45 12.58 0 top
CH202  22U_0603_6.3V6M  [C_0603]  101.86 11.5 0 top
CH203  0.1U_0402_10V7K  [C_0402]  91.44 10.66 90 top
CH204  0.1U_0402_10V7K  [C_0402]  84.58 5.72 0 top
CI1  0.1U_0402_25V6  [C_0402]  24.52 87.58 270 top
CI2  0.1U_0402_25V6  [C_0402]  330.46 60.6 270 bottom
CI3  0.1U_0402_10V7K  [C_0402]  323.33 34.3 0 bottom
CI4  0.01U_0402_16V7K  [C_0402]  315.93 29.73 180 bottom
CI5  0.1U_0402_10V7K  [C_0402]  321.18 27.75 90 bottom
CI6  0.1U_0402_10V7K  [C_0402]  320.3 27.75 90 bottom
CI7  0.1U_0402_10V7K  [C_0402]  319.41 27.75 90 bottom
CI8  0.1U_0402_10V7K  [C_0402]  318.52 27.75 90 bottom
CI9  0.1U_0402_10V7K  [C_0402]  20.51 104.45 90 bottom
CI10  0.1U_0402_10V7K  [C_0402]  19.56 104.45 90 bottom
CI11  47U_0805_6.3V6M  [C_0805]  20.26 108.12 90 top
CI12  10U_0603_6.3V6M  [C_0603]  18.8 108.02 270 top
CI13  0.1U_0402_25V6  [C_0402]  18.86 109.34 90 top
CI16  0.1U_0402_10V7K  [C_0402]  320.3 36.13 90 bottom
CI17  47U_0805_6.3V6M  [C_0805]  331.43 69.48 180 bottom
CI18  10U_0603_6.3V6M  [C_0603]  331.03 67.95 180 bottom
CI19  0.1U_0402_25V6  [C_0402]  331.1 66.87 180 bottom
CI20  0.1U_0402_10V7K  [C_0402]  321.18 36.13 90 bottom
CI21  0.1U_0402_10V7K  [C_0402]  26.16 86.67 90 top
CI22  0.1U_0402_10V7K  [C_0402]  324.82 53.48 90 top
CLRP1  SHORT PADS  [SHORTPADS]  106.81 2.42 270 bottom
CN1  22U_0603_6.3V6M  [C_0603]  333.69 104.72 180 top
CN2  .1U_0402_16V7K  [C_0402]  333.62 106.75 0 top
CN6  22U_0603_6.3V6M  [C_0603]  334.65 104.72 0 top
CN7  .1U_0402_16V7K  [C_0402]  333.62 105.86 0 top
CN8  .1U_0402_16V7K  [C_0402]  333.62 107.64 0 top
CN9  1000P_0402_50V7K  [C_0402]  333.62 108.53 0 top
CN20  0.1U_0402_10V7K  [C_0402]  330.96 80.65 90 bottom
CN21  0.1U_0402_10V7K  [C_0402]  332.11 80.65 90 bottom
CN22  2200P_0402_25V7K  [C_0402]  335.2 103.39 0 top
CR1  0.1U_0402_10V7K  [C_0402]  333.93 36.79 0 bottom
CR2  0.1U_0402_10V7K  [C_0402]  333.93 38.17 0 bottom
CR3  1U_0402_6.3V6K  [C_0402]  337.54 40.8 90 bottom
CR4  10U_0603_6.3V6M  [C_0603]  332.93 36.97 180 bottom
CR5  0.1U_0402_10V7K  [C_0402]  336.45 32.91 270 bottom
CR6  4.7U_0603_6.3V6K  [C_0603]  332.93 38.17 180 bottom
CR7  0.1U_0402_10V7K  [C_0402]  327.43 27.19 0 bottom
CR8  10P_0402_25V8J  [C_0402]  335.15 41.74 270 bottom
CR9  0.1U_0402_10V7K  [C_0402]  327.43 28.2 0 bottom
CR10  0.1U_0402_10V7K  [C_0402]  330.73 30.55 0 bottom
CR11  0.1U_0402_10V7K  [C_0402]  344.68 37.4 90 bottom
CR12  4.7U_0603_6.3V6K  [C_0603]  345.76 36.71 90 bottom
CR13  0.1U_0402_10V7K  [C_0402]  330.73 31.57 0 bottom
CR14  10U_0603_6.3V6M  [C_0603]  328.13 49.98 270 top
CR15  0.1U_0402_10V7K  [C_0402]  328.13 50.92 90 top
CR16  1U_0402_6.3V6K  [C_0402]  343.35 39.68 90 bottom
CR17  4.7U_0603_6.3V6K  [C_0603]  347.54 48.21 0 bottom
CR18  0.1U_0402_10V7K  [C_0402]  347.54 47.06 0 bottom
CS12  1000P_0402_50V7K  [C_0402]  236.73 12.51 90 bottom
CS13  .1U_0402_16V7K  [C_0402]  238.51 12.51 90 bottom
CS14  1U_0402_6.3V6K  [C_0402]  237.62 12.51 90 bottom
CS15  10U_0603_6.3V6M  [C_0603]  239.69 12.84 0 bottom
CS17  0.01U_0402_16V7K  [C_0402]  232.92 13.42 270 bottom
CS18  0.01U_0402_16V7K  [C_0402]  233.81 13.42 270 bottom
CS19  0.01U_0402_16V7K  [C_0402]  235.71 13.42 270 bottom
CS20  0.01U_0402_16V7K  [C_0402]  234.82 13.42 270 bottom
CT1  0.22U_0201_6.3V6M  [C_0201]  30.61 33.18 90 bottom
CT2  0.22U_0201_6.3V6M  [C_0201]  31.88 33.77 270 bottom
CT3  0.22U_0201_6.3V6M  [C_0201]  31.18 33.18 90 bottom
CT4  0.22U_0201_6.3V6M  [C_0201]  32.45 33.77 270 bottom
CT5  0.22U_0201_6.3V6M  [C_0201]  28.07 33.18 90 bottom
CT6  0.22U_0201_6.3V6M  [C_0201]  29.27 33.77 270 bottom
CT7  0.22U_0201_6.3V6M  [C_0201]  28.64 33.18 90 bottom
CT8  0.22U_0201_6.3V6M  [C_0201]  29.85 33.77 270 bottom
CT17  0.1U_0201_6.3V6K  [C_0201]  34.76 42.87 0 bottom
CT18  0.1U_0201_6.3V6K  [C_0201]  34.76 42.24 0 bottom
CT19  0.1U_0201_6.3V6K  [C_0201]  35.94 41.16 0 bottom
CT20  0.1U_0201_6.3V6K  [C_0201]  35.94 41.79 0 bottom
CT21  0.1U_0201_6.3V6K  [C_0201]  34.76 40.14 0 bottom
CT22  0.1U_0201_6.3V6K  [C_0201]  34.76 40.78 0 bottom
CT23  0.1U_0201_6.3V6K  [C_0201]  36.17 39.06 0 bottom
CT24  0.1U_0201_6.3V6K  [C_0201]  36.17 39.63 0 bottom
CT25  0.1U_0201_6.3V6K  [C_0201]  33.36 40.78 0 top
CT26  0.1U_0201_6.3V6K  [C_0201]  33.36 41.35 0 top
CT29  0.1U_0201_6.3V6K  [C_0201]  34.76 37.92 0 bottom
CT30  0.1U_0201_6.3V6K  [C_0201]  34.76 38.55 0 bottom
CT31  0.1U_0201_6.3V6K  [C_0201]  36.17 36.03 0 bottom
CT32  0.1U_0201_6.3V6K  [C_0201]  36.17 36.66 0 bottom
CT33  0.1U_0201_6.3V6K  [C_0201]  36.16 34.55 0 bottom
CT34  0.1U_0201_6.3V6K  [C_0201]  36.16 35.19 0 bottom
CT35  0.1U_0201_6.3V6K  [C_0201]  33.77 33.79 270 bottom
CT36  0.1U_0201_6.3V6K  [C_0201]  34.41 33.79 270 bottom
CT37  0.22U_0201_6.3V6M  [C_0201]  20.18 38.24 180 bottom
CT38  0.22U_0201_6.3V6M  [C_0201]  20.18 38.81 180 bottom
CT39  0.22U_0201_6.3V6M  [C_0201]  19.93 36.47 180 bottom
CT40  0.22U_0201_6.3V6M  [C_0201]  19.93 37.04 180 bottom
CT41  0.1U_0201_6.3V6K  [C_0201]  33.36 38.93 0 top
CT42  0.1U_0201_6.3V6K  [C_0201]  33.36 38.36 0 top
CT43  10P_0201_50V8J  [C_0201]  21.87 32.13 270 bottom
CT44  10P_0201_50V8J  [C_0201]  26.48 32.12 270 bottom
CT47  0.1U_0201_6.3V6K  [C_0201]  41.75 28.08 0 bottom
CT50  1U_0201_6.3V6M  [C_0201]  34.39 42.81 180 top
CT52  1U_0201_6.3V6M  [C_0201]  19.31 45.86 90 bottom
CT53  10U_0402_6.3V6M  [C_0402]  20.33 41.97 270 bottom
CT54  10U_0402_6.3V6M  [C_0402]  19.44 41.97 270 bottom
CT55  10U_0402_6.3V6M  [C_0402]  20.08 45.75 90 bottom
CT56  10U_0402_6.3V6M  [C_0402]  18.54 45.35 90 bottom
CT62  1U_0201_6.3V6M  [C_0201]  27.19 45.39 0 top
CT63  1U_0201_6.3V6M  [C_0201]  28.03 43.7 0 top
CT64  1U_0201_6.3V6M  [C_0201]  27.19 46 0 top
CT65  1U_0201_6.3V6M  [C_0201]  27.22 40.24 180 top
CT66  1U_0201_6.3V6M  [C_0201]  30.65 38.26 180 top
CT67  1U_0201_6.3V6M  [C_0201]  31.75 38.15 270 top
CT68  1U_0201_6.3V6M  [C_0201]  32.39 38.15 270 top
CT71  1U_0201_6.3V6M  [C_0201]  28.16 35.86 270 top
CT72  1U_0201_6.3V6M  [C_0201]  28.92 35.86 270 top
CT74  1U_0201_6.3V6M  [C_0201]  22.26 43.7 180 top
CT80  1U_0201_6.3V6M  [C_0201]  26 35.9 270 top
CT81  1U_0201_6.3V6M  [C_0201]  26.63 35.86 270 top
CT82  1U_0201_6.3V6M  [C_0201]  27.39 35.86 270 top
CT83  1U_0201_6.3V6M  [C_0201]  22.26 43.06 180 top
CT84  1U_0201_6.3V6M  [C_0201]  22.26 44.33 180 top
CT85  1U_0201_6.3V6M  [C_0201]  22.26 41.79 180 top
CT86  1U_0201_6.3V6M  [C_0201]  22.26 42.43 180 top
CT88  47U_0603_6.3V6M  [C_0603]  23.61 45.61 180 top
CT89  47U_0603_6.3V6M  [C_0603]  23.24 46.81 90 top
CT90  47U_0603_6.3V6M  [C_0603]  22.16 48.14 180 top
CT93  1U_0201_6.3V6M  [C_0201]  28.55 37.63 180 top
CT94  1U_0201_6.3V6M  [C_0201]  28.79 38.24 0 top
CT95  10U_0402_6.3V6M  [C_0402]  22.25 39.21 180 top
CT96  10U_0402_6.3V6M  [C_0402]  22.24 38.3 180 top
CT97  10U_0402_6.3V6M  [C_0402]  22.25 41 180 top
CT98  10U_0402_6.3V6M  [C_0402]  22.25 40.12 180 top
CT99  1U_0201_6.3V6M  [C_0201]  25.49 38.31 270 top
CT100  1U_0201_6.3V6M  [C_0201]  25.46 38.93 90 top
CT101  1U_0201_6.3V6M  [C_0201]  31.79 44.2 180 top
CT102  1U_0201_6.3V6M  [C_0201]  32.3 42.93 180 top
CT103  1U_0201_6.3V6M  [C_0201]  32.32 43.56 180 top
CT105  10U_0603_6.3V6M  [C_0603]  16.96 33.63 90 bottom
CT106  470P_0402_50V7K  [C_0402]  15.18 32.09 270 bottom
CT107  0.1U_0201_6.3V6K  [C_0201]  33.36 39.57 0 top
CT108  0.1U_0201_6.3V6K  [C_0201]  33.36 40.14 0 top
CT120  0.47U_0402_25V6K  [C_0402]  11.81 66.76 270 bottom
CT121  0.47U_0402_25V6K  [C_0402]  10.92 66.76 270 bottom
CT122  0.47U_0402_25V6K  [C_0402]  8 65.11 270 bottom
CT123  0.47U_0402_25V6K  [C_0402]  8.13 66.73 90 bottom
CT141  1U_0201_6.3V6M  [C_0201]  25.78 46.02 270 top
CT142  1U_0201_6.3V6M  [C_0201]  25.15 46.02 270 top
CT143  1U_0201_6.3V6M  [C_0201]  24.3 42.3 180 top
CT144  2.2U_0402_6.3V6M  [C_0402]  18.75 57.92 180 bottom
CT145  1U_0201_6.3V6M  [C_0201]  22.09 60.99 0 top
CT146  10U_0402_6.3V6M  [C_0402]  20.92 60.38 90 top
CT147  22U_0603_6.3V6M  [C_0603]  27.88 54.45 0 bottom
CT148  22U_0603_6.3V6M  [C_0603]  27.88 53.23 0 bottom
CT149  22U_0603_6.3V6M  [C_0603]  27.88 55.67 0 bottom
CT150  22U_0603_6.3V6M  [C_0603]  27.88 56.88 0 bottom
CT151  2.2U_0402_6.3V6M  [C_0402]  19.44 62.11 180 bottom
CT152  2.2U_0402_6.3V6M  [C_0402]  20.83 54.63 270 bottom
CT153  1U_0603_25V6  [C_0603]  27.88 65.67 90 bottom
CT155  4.7U_0603_25V6K  [C_0603]  23.85 56.55 180 top
CT157  1U_0603_25V6  [C_0603]  28.45 61.16 270 bottom
CT158  0.22U_0402_10V6K  [C_0402]  25.66 60.38 90 top
CT159  220P_0402_50V7K  [C_0402]  25.59 63.24 90 top
CT160  220P_0402_50V7K  [C_0402]  27.1 62.81 90 top
CT161  10U_0402_6.3V6M  [C_0402]  21.48 55.83 90 top
CT162  10U_0603_6.3V6M  [C_0603]  15.69 33.63 90 bottom
CT163  1U_0201_6.3V6M  [C_0201]  28.44 40.19 180 top
CT164  47U_0603_6.3V6M  [C_0603]  31.23 34.87 0 top
CT165  47U_0603_6.3V6M  [C_0603]  31.79 33.65 0 top
CT170  0.1U_0201_6.3V6K  [C_0201]  27.27 100.02 0 bottom
CT171  0.1U_0201_6.3V6K  [C_0201]  19.24 48.18 270 bottom
CT172  0.1U_0201_6.3V6K  [C_0201]  25.12 100.28 180 bottom
CT173  0.1U_0201_6.3V6K  [C_0201]  25.27 96.19 270 bottom
CV121  0.1U_0402_10V7K  [C_0402]  201.74 79.31 90 top
CV122  1U_0603_10V6K  [C_0603]  201.8 106.12 180 bottom
CV123  4.7U_0805_25V6-K  [C_0805]  201.96 104.59 180 bottom
CV156  8.2P_0402_50V8D  [C_0402]  64.95 32.65 0 top
CV157  10U_0603_6.3V6M  [C_0603]  64.11 30.49 0 top
CV158  0.1U_0402_10V7K  [C_0402]  63.25 22.03 90 bottom
CV159  0.1U_0402_10V7K  [C_0402]  64.14 22.03 90 bottom
CV160  0.1U_0402_10V7K  [C_0402]  65.15 22.03 90 bottom
CV161  0.1U_0402_10V7K  [C_0402]  66.04 22.03 90 bottom
CV162  0.1U_0402_10V7K  [C_0402]  69.47 22.03 90 bottom
CV163  0.1U_0402_10V7K  [C_0402]  70.36 22.03 90 bottom
CV164  0.1U_0402_10V7K  [C_0402]  71.38 22.03 90 bottom
CV165  0.1U_0402_10V7K  [C_0402]  72.26 22.03 90 bottom
CV166  0.1U_0402_10V7K  [C_0402]  62.23 22.03 90 bottom
CV167  0.1U_0402_10V7K  [C_0402]  61.34 22.03 90 bottom
CV168  1U_0603_25V6  [C_0603]  47.31 21.73 0 bottom
CV169  0.1U_0402_25V6  [C_0402]  51.74 25.6 0 bottom
CV170  0.1U_0201_6.3V6K  [C_0201]  25.41 50.22 270 bottom
CV171  0.1U_0201_6.3V6K  [C_0201]  26 50.22 270 bottom
CV172  0.1U_0201_6.3V6K  [C_0201]  28.89 48.24 270 bottom
CV173  0.1U_0201_6.3V6K  [C_0201]  29.47 48.24 270 bottom
CV174  0.1U_0201_6.3V6K  [C_0201]  27.75 48.24 270 bottom
CV175  0.1U_0201_6.3V6K  [C_0201]  28.32 48.24 270 bottom
CV176  0.1U_0201_6.3V6K  [C_0201]  26.62 48 270 bottom
CV177  0.1U_0201_6.3V6K  [C_0201]  27.18 47.99 270 bottom
CV178  0.1U_0402_10V7K  [C_0402]  14.73 88.86 270 top
CV179  10U_0603_6.3V6M  [C_0603]  15.88 89.23 270 top
CV180  0.1U_0402_25V6  [C_0402]  15.63 91.19 180 bottom
CV181  0.1U_0402_25V6  [C_0402]  15.63 90.31 180 bottom
CV182  0.1U_0402_25V6  [C_0402]  15.63 89.42 180 bottom
CV183  .1U_0402_16V7K  [C_0402]  62.17 30.95 270 top
CV184  8.2P_0402_50V8D  [C_0402]  61.28 30.95 270 top
CV363  0.1U_0402_25V6  [C_0402]  242.08 103.54 180 top
CV499  0.1U_0402_10V7K  [C_0402]  245.89 47.54 90 top
CV794  0.1U_0402_10V7K  [C_0402]  242.08 104.45 180 top
CV796  1U_0402_6.3V6K  [C_0402]  242.08 105.38 180 top
CV798  4.7U_0603_6.3V6K  [C_0603]  242.08 106.47 180 top
CV817  0.1U_0402_10V7K  [C_0402]  208.22 51.49 90 top
CV818  0.22U_0201_6.3V6M  [C_0201]  191.42 65.45 180 top
CV819  0.22U_0201_6.3V6M  [C_0201]  191.42 64.81 180 top
CV820  0.22U_0201_6.3V6M  [C_0201]  193.07 66.46 180 top
CV821  0.22U_0201_6.3V6M  [C_0201]  193.07 65.83 180 top
CV822  0.22U_0201_6.3V6M  [C_0201]  191.42 66.85 180 top
CV823  0.22U_0201_6.3V6M  [C_0201]  191.42 67.48 180 top
CV824  0.22U_0201_6.3V6M  [C_0201]  193.07 68.5 180 top
CV825  0.22U_0201_6.3V6M  [C_0201]  193.07 67.86 180 top
CV826  0.22U_0201_6.3V6M  [C_0201]  191.42 68.88 180 top
CV827  0.22U_0201_6.3V6M  [C_0201]  191.42 69.51 180 top
CV828  0.22U_0201_6.3V6M  [C_0201]  193.07 70.53 180 top
CV829  0.22U_0201_6.3V6M  [C_0201]  193.07 69.89 180 top
CV830  0.22U_0201_6.3V6M  [C_0201]  191.42 70.91 180 top
CV831  0.22U_0201_6.3V6M  [C_0201]  191.42 71.54 180 top
CV832  0.22U_0201_6.3V6M  [C_0201]  193.07 72.56 180 top
CV833  0.22U_0201_6.3V6M  [C_0201]  193.07 71.93 180 top
CV834  0.22U_0201_6.3V6M  [C_0201]  191.42 73.58 180 top
CV835  0.22U_0201_6.3V6M  [C_0201]  191.42 72.94 180 top
CV836  0.22U_0201_6.3V6M  [C_0201]  193.07 73.96 180 top
CV837  0.22U_0201_6.3V6M  [C_0201]  193.07 74.59 180 top
CV838  0.22U_0201_6.3V6M  [C_0201]  191.42 75.61 180 top
CV839  0.22U_0201_6.3V6M  [C_0201]  191.42 74.97 180 top
CV840  0.22U_0201_6.3V6M  [C_0201]  194.02 75.93 180 top
CV841  0.22U_0201_6.3V6M  [C_0201]  194.02 76.56 180 top
CV842  0.22U_0201_6.3V6M  [C_0201]  192.5 77.64 180 top
CV843  0.22U_0201_6.3V6M  [C_0201]  192.5 77.01 180 top
CV844  0.22U_0201_6.3V6M  [C_0201]  194.02 78.02 180 top
CV845  0.22U_0201_6.3V6M  [C_0201]  194.02 78.66 180 top
CV846  0.22U_0201_6.3V6M  [C_0201]  192.5 78.97 180 top
CV847  0.22U_0201_6.3V6M  [C_0201]  192.5 79.61 180 top
CV848  0.22U_0201_6.3V6M  [C_0201]  194.02 79.99 180 top
CV849  0.22U_0201_6.3V6M  [C_0201]  194.02 80.62 180 top
CV850  0.1U_0402_10V7K  [C_0402]  219.39 79.13 180 top
CV851  0.1U_0402_10V7K  [C_0402]  204.05 64.4 0 top
CV852  0.1U_0402_10V7K  [C_0402]  201.75 63.51 225 top
CV853  0.1U_0402_10V7K  [C_0402]  227.18 46.77 0 top
CV854  0.1U_0402_10V7K  [C_0402]  201.88 61.41 180 top
CV855  10U_0603_6.3V6M  [C_0603]  197.36 98.5 270 top
CV856  47U_0805_6.3V6M  [C_0805]  198.95 98.84 270 top
CV857  10P_0402_50V8J  [C_0402]  216.46 51.13 0 top
CV858  10P_0402_50V8J  [C_0402]  219.15 51.13 180 top
CV859  1U_0402_6.3V6K  [C_0402]  200.98 75.27 270 top
CV860  1U_0402_6.3V6K  [C_0402]  200.45 72.72 180 top
CV861  4.7U_0603_6.3V6K  [C_0603]  201.3 101.8 180 bottom
CV862  22U_0603_6.3V6M  [C_0603]  227.14 60.59 270 bottom
CV863  22U_0603_6.3V6M  [C_0603]  221.11 88.02 270 top
CV864  10U_0603_6.3V6M  [C_0603]  218.44 87.7 0 top
CV865  1U_0402_6.3V6K  [C_0402]  200.36 76.97 180 top
CV866  1U_0402_6.3V6K  [C_0402]  195.47 61.54 180 top
CV867  4.7U_0603_6.3V6K  [C_0603]  201.3 100.53 180 bottom
CV868  10U_0603_6.3V6M  [C_0603]  199.9 99.26 0 bottom
CV869  22U_0603_6.3V6M  [C_0603]  196.53 86.5 90 top
CV870  22U_0603_6.3V6M  [C_0603]  221.64 80.07 0 top
CV871  22U_0603_6.3V6M  [C_0603]  225.74 60.59 270 bottom
CV872  22U_0603_6.3V6M  [C_0603]  222.25 81.73 0 top
CV873  10U_0603_6.3V6M  [C_0603]  222.44 86.31 90 top
CV874  1U_0402_6.3V6K  [C_0402]  201.72 68.37 0 top
CV875  1U_0402_6.3V6K  [C_0402]  202.05 76.28 0 top
